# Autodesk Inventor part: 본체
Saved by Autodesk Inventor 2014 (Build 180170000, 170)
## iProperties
Created: 2026-03
Part Number: 본체
Material: 알루미늄 6061
Document SubType Name: Modeling
Designer: dg
Density: 2.71 g/cm^3
Appearance: 알루미늄 - 평지
Mass: 495.493 g
Surface Area: 439.688 cm^2
Volume: 182.839 cm^3
Author: jhkim
Creation Date: 2025-06-27
Sending System: Autodesk Inventor 2026
Preprocessor: ST-DEVELOPER v20.1
Author: dg
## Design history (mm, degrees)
node "본체1"
node "솔리드1"
node "기준1"
